Omron CX-Programmer project NuevoProyecto (CX-Programmer 9.50)

# PLC NewPLC1: CQM1 CPU21

## Program P7_6_2 (no task)
Local symbols
Ab 100.01 BOOL
As 100.00 BOOL
B 100.02 BOOL
C 100.03 BOOL
Etapa_0 10.00 BOOL
Etapa_1 10.01 BOOL
Etapa_10 10.06 BOOL
Etapa_11 10.07 BOOL
Etapa_12 10.08 BOOL
Etapa_13 10.09 BOOL
Etapa_14 10.10 BOOL
Etapa_2 10.02 BOOL
Etapa_3 10.03 BOOL
Etapa_4 10.04 BOOL
Etapa_5 10.05 BOOL
FS_Etapa_2 15.00 BOOL
FS_Etapa_4 15.01 BOOL
a_0 0.01 BOOL
a_1 0.02 BOOL
a_2 0.03 BOOL
b_0 0.04 BOOL
b_1 0.05 BOOL
c_0 0.06 BOOL
c_1 0.07 BOOL
m 0.00 BOOL

### Section Secci๓n1_GRAFCET_principal
; Etapas X0 ... X5

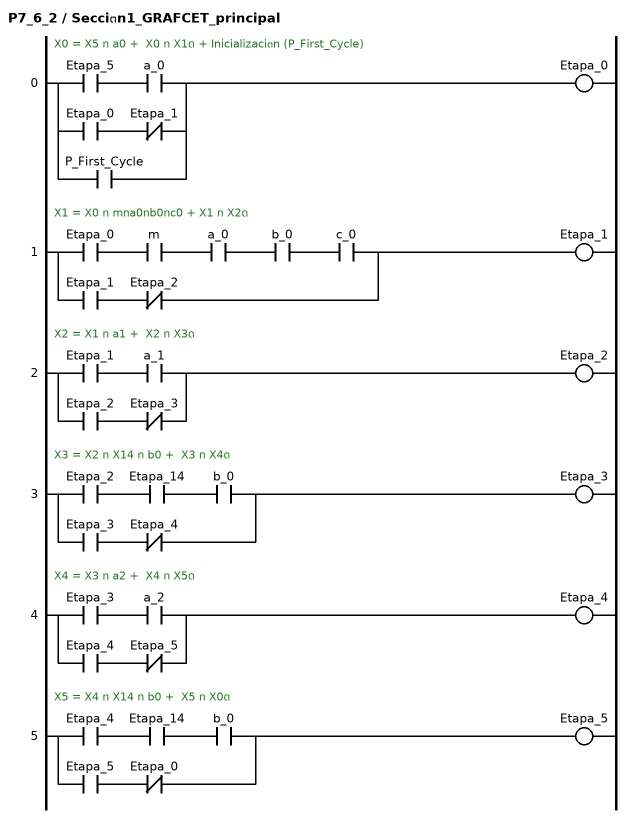
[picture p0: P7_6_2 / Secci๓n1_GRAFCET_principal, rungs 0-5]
; rung 0: X0 = X5 ท a0 +  X0 ท X1ด + Inicializaci๓n (P_First_Cycle)
LD Etapa_5
AND a_0
LD Etapa_0
ANDNOT Etapa_1
ORLD
OR P_First_Cycle
OUT Etapa_0
; rung 1: X1 = X0 ท mทa0ทb0ทc0 + X1 ท X2ด
LD Etapa_0
AND m
AND a_0
AND b_0
AND c_0
LD Etapa_1
ANDNOT Etapa_2
ORLD
OUT Etapa_1
; rung 2: X2 = X1 ท a1 +  X2 ท X3ด
LD Etapa_1
AND a_1
LD Etapa_2
ANDNOT Etapa_3
ORLD
OUT Etapa_2
; rung 3: X3 = X2 ท X14 ท b0 +  X3 ท X4ด
LD Etapa_2
AND Etapa_14
AND b_0
LD Etapa_3
ANDNOT Etapa_4
ORLD
OUT Etapa_3
; rung 4: X4 = X3 ท a2 +  X4 ท X5ด
LD Etapa_3
AND a_2
LD Etapa_4
ANDNOT Etapa_5
ORLD
OUT Etapa_4
; rung 5: X5 = X4 ท X14 ท b0 +  X5 ท X0ด
LD Etapa_4
AND Etapa_14
AND b_0
LD Etapa_5
ANDNOT Etapa_0
ORLD
OUT Etapa_5

### Section Secci๓n2_GRAFCET_auxiliar
; Etapas X10 ... X14

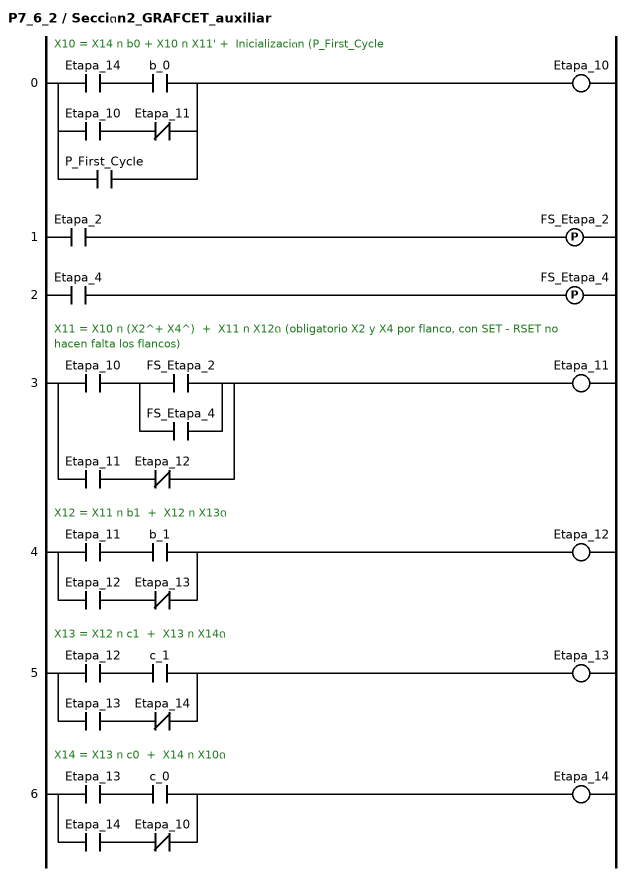
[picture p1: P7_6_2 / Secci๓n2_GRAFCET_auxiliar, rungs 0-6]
; rung 0: X10 = X14 ท b0 + X10 ท X11' +  Inicializaci๓n (P_First_Cycle
LD Etapa_14
AND b_0
LD Etapa_10
ANDNOT Etapa_11
ORLD
OR P_First_Cycle
OUT Etapa_10
; rung 1
LD Etapa_2
DIFU(13) FS_Etapa_2
; rung 2
LD Etapa_4
DIFU(13) FS_Etapa_4
; rung 3: X11 = X10 ท (X2^+ X4^)  +  X11 ท X12ด (obligatorio X2 y X4 por flanco, con SET - RSET no hacen falta los flancos)
LD Etapa_10
LD FS_Etapa_2
OR FS_Etapa_4
ANDLD
LD Etapa_11
ANDNOT Etapa_12
ORLD
OUT Etapa_11
; rung 4: X12 = X11 ท b1  +  X12 ท X13ด
LD Etapa_11
AND b_1
LD Etapa_12
ANDNOT Etapa_13
ORLD
OUT Etapa_12
; rung 5: X13 = X12 ท c1  +  X13 ท X14ด
LD Etapa_12
AND c_1
LD Etapa_13
ANDNOT Etapa_14
ORLD
OUT Etapa_13
; rung 6: X14 = X13 ท c0  +  X14 ท X10ด
LD Etapa_13
AND c_0
LD Etapa_14
ANDNOT Etapa_10
ORLD
OUT Etapa_14

### Section Secci๓n3_Salidas

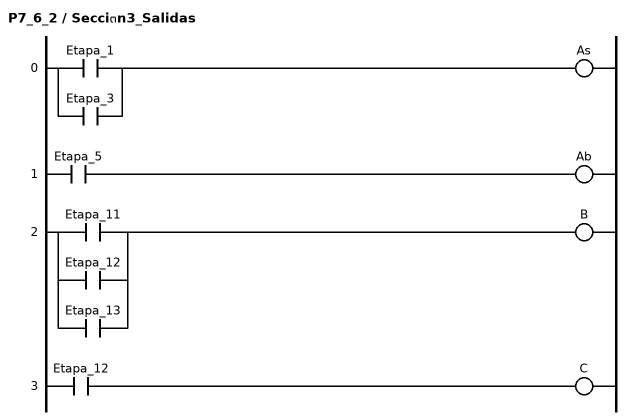
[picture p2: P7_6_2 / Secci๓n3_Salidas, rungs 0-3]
; rung 0
LD Etapa_1
OR Etapa_3
OUT As
; rung 1
LD Etapa_5
OUT Ab
; rung 2
LD Etapa_11
OR Etapa_12
OR Etapa_13
OUT B
; rung 3
LD Etapa_12
OUT C

### Section Secci๓n4_END
; rung 0: Fin de programa
END(01)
